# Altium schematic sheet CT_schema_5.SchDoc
size 422 x 246 mm
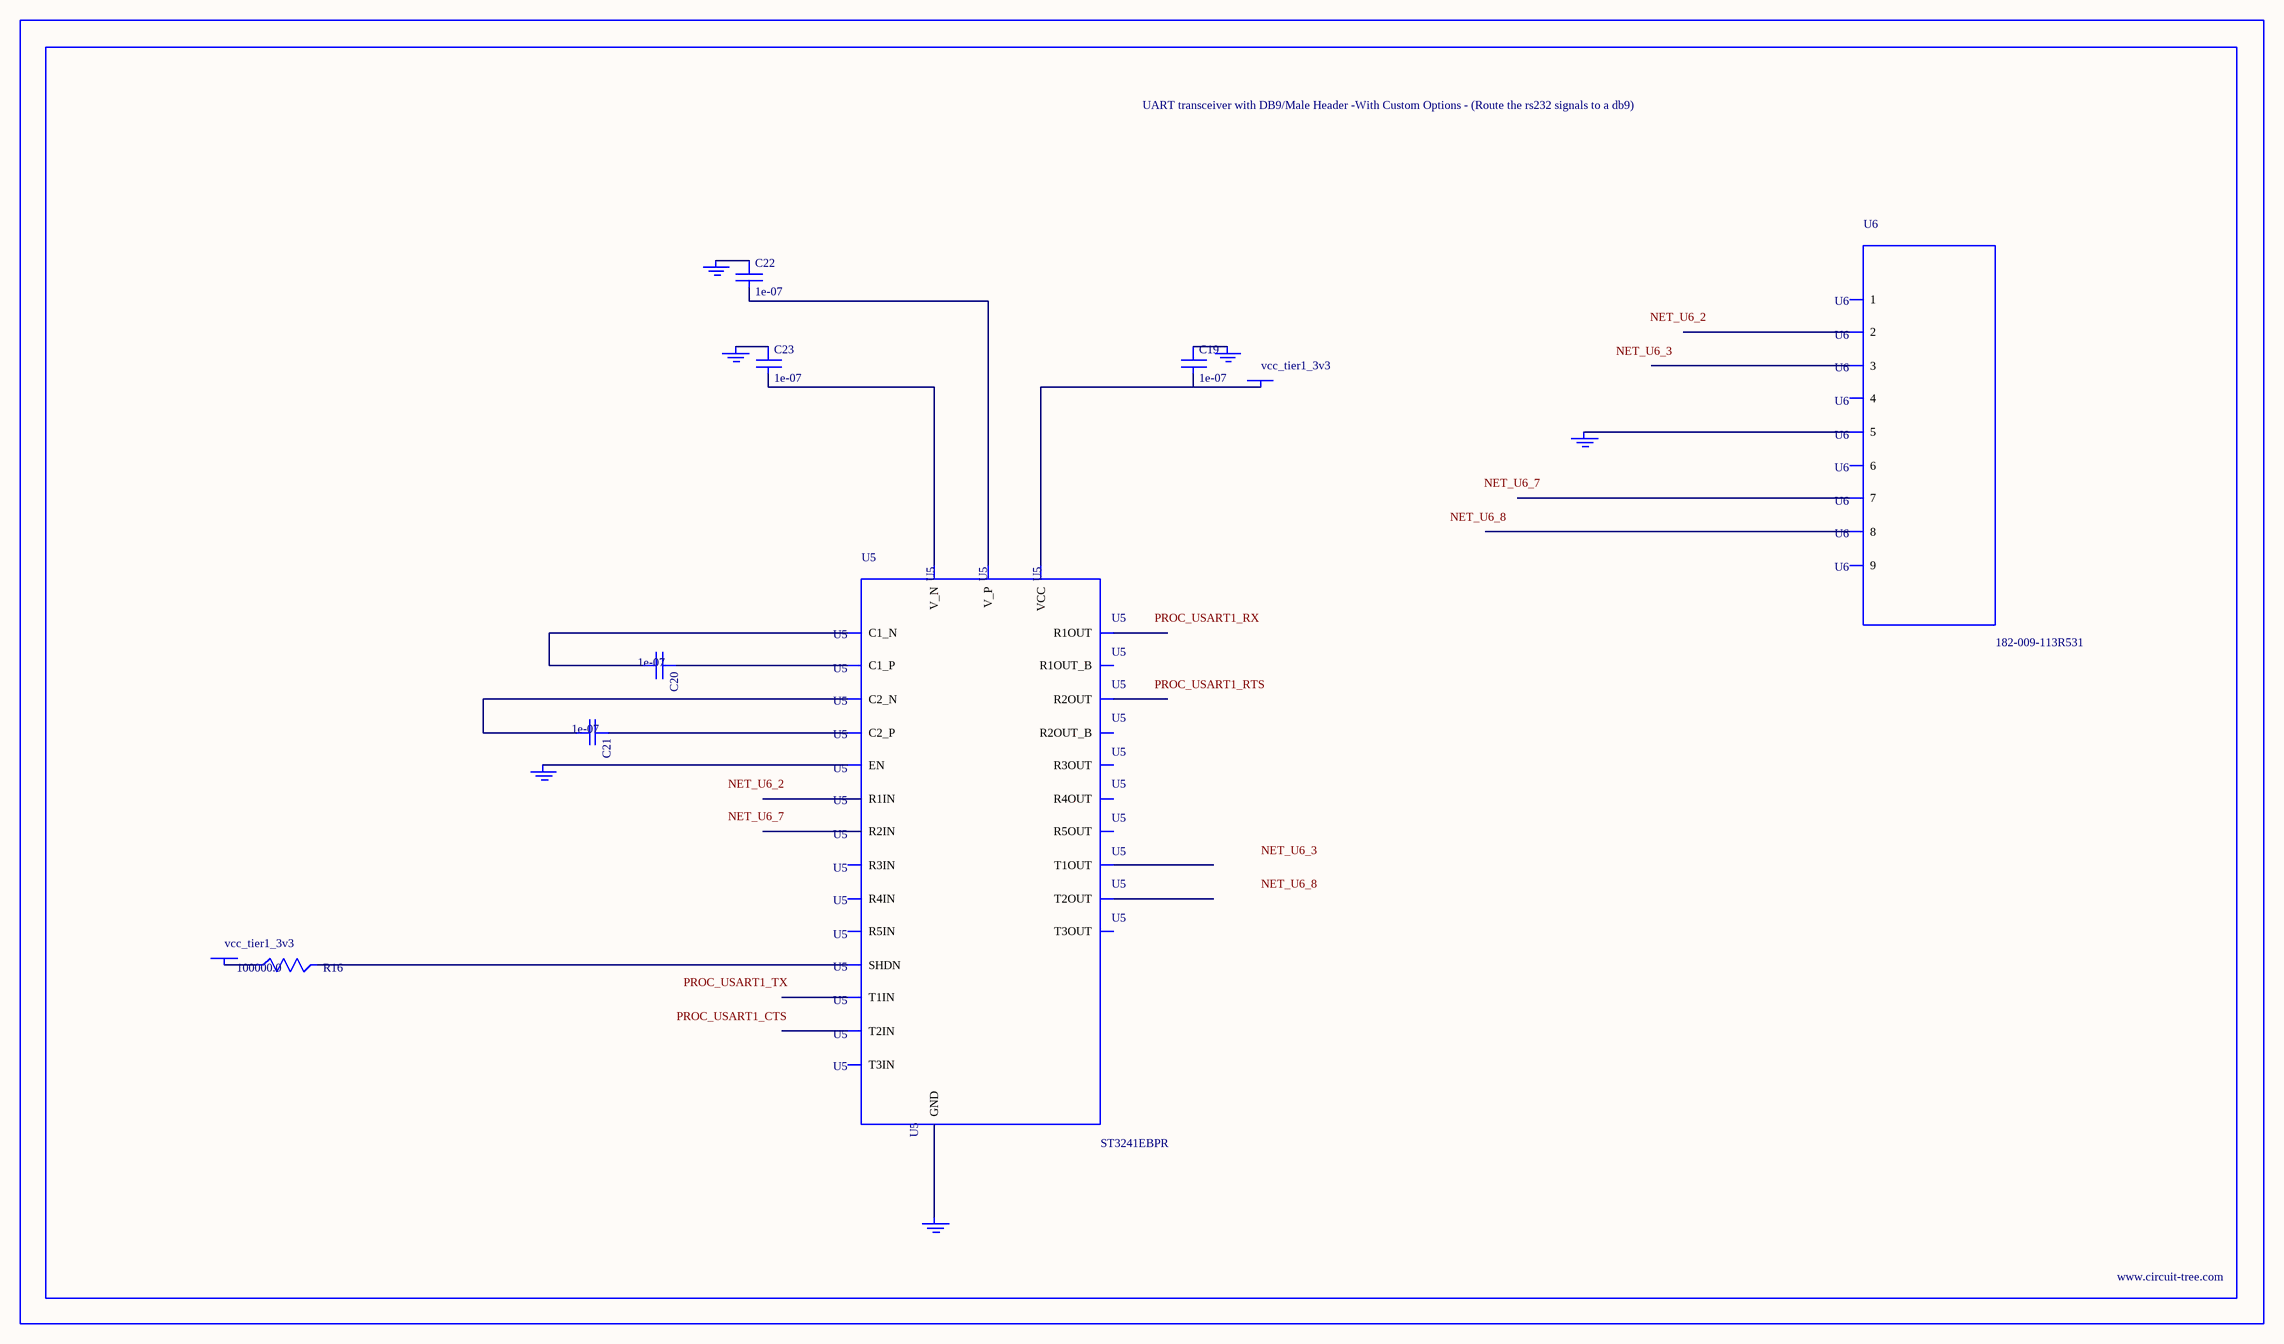
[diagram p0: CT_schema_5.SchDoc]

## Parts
BORDER4  (no value)
C19  1e-07  [C0402]
C20  1e-07  [C0402]
C21  1e-07  [C0402]
C22  1e-07  [C0402]
C23  1e-07  [C0402]
GND_INSTANCE_4_0  (no value)
GND_INSTANCE_4_1  (no value)
GND_INSTANCE_4_2  (no value)
GND_INSTANCE_4_3  (no value)
GND_INSTANCE_4_4  (no value)
GND_INSTANCE_4_5  (no value)
POWER_INSTANCE_4_0  vcc_tier1_3v3
POWER_INSTANCE_4_1  vcc_tier1_3v3
R16  100000.0  [R0603]
U5  ST3241EBPR  [SSOP-28]
U6  182-009-113R531  [182-009-MALE]

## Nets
NetC19_1: C19.1 GND_INSTANCE_4_2.0(GND)
NetC19_2: C19.2 POWER_INSTANCE_4_1.0(PWR) U5.26(VCC)
NetC20_1: C20.1 U5.28(C1_P)
NetC20_2: C20.2 U5.24(C1_N)
NetC21_1: C21.1 U5.1(C2_P)
NetC21_2: C21.2 U5.2(C2_N)
NetC22_1: C22.1 GND_INSTANCE_4_3.0(GND)
NetC22_2: C22.2 U5.27(V_P)
NetC23_1: C23.1 GND_INSTANCE_4_0.0(GND)
NetC23_2: C23.2 U5.3(V_N)
NetGND_INSTANCE_4_1_0: GND_INSTANCE_4_1.0(GND) U5.23(EN)
NetGND_INSTANCE_4_4_0: GND_INSTANCE_4_4.0(GND) U5.25(GND)
NetGND_INSTANCE_4_5_0: GND_INSTANCE_4_5.0(GND) U6.5
NetPOWER_INSTANCE_4_0_0: POWER_INSTANCE_4_0.0(PWR) R16.1
NetR16_2: R16.2 U5.22(SHDN)

Not connected (* = marked no-connect by the designer): U5 4(R1IN) 5(R2IN) 6(R3IN) 7(R4IN) 8(R5IN) 9(T1OUT) 10(T2OUT) 11(T3OUT) 12(T3IN) 13(T2IN) 14(T1IN) 15(R5OUT) 16(R4OUT) 17(R3OUT) 18(R2OUT) 19(R1OUT) 20(R2OUT_B) 21(R1OUT_B); U6 1 2 3 4 6 7 8 9

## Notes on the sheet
- Labels drawn without touching a wire or pin: NET_U6_2, NET_U6_3, NET_U6_7, NET_U6_8, PROC_USART1_CTS, PROC_USART1_RTS, PROC_USART1_RX, PROC_USART1_TX

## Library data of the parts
BORDER4 = BORDER_PAGE4
C19-C23 = C0402C104K3RACTU
GND_INSTANCE_4_0-GND_INSTANCE_4_5 = GND
POWER_INSTANCE_4_0 POWER_INSTANCE_4_1 = PWR
R16 = RC0603JR-07100KL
